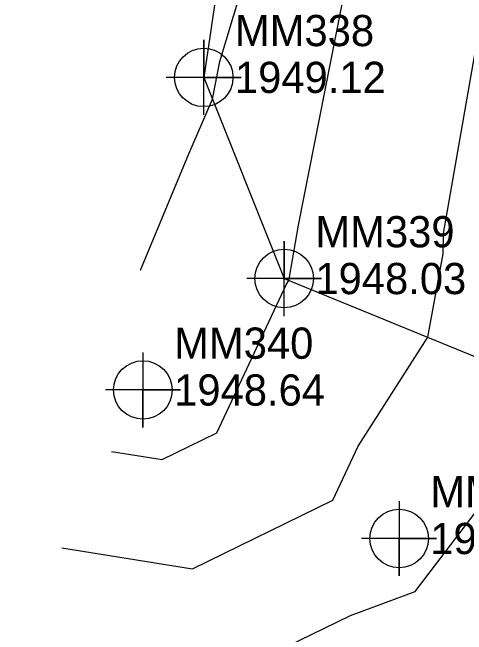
# Model space of a CAD drawing. Extents: x 1004378 to 1005103, y 553854 to 554288.
# Drawn here: x 1004892.91 to 1004929.28, y 553980.98 to 554030.8 of the extents above; entities that cross this region are included whole.
import ezdxf

# ---------------------------------------------------------------- set-up
doc = ezdxf.new("R2010")
doc.units = 0
for name, color, linetype in [('DTM Contours Minor', 7, 'Continuous'), ('Exist DTM Regular Point CELL', 7, 'Continuous'), ('Exist DTM Regular Point Cogo Elevation', 7, 'Continuous'), ('Exist DTM Regular Point Cogo Number', 7, 'Continuous'), ('Exist Roads Soil', 7, 'Continuous'), ('Exist Roads Soil Cogo Elevation', 7, 'Continuous'), ('Exist Roads Soil Cogo Number', 7, 'Continuous'), ('Exist Roads Soil Cogo Point CELL', 7, 'Continuous')]:
    doc.layers.add(name, color=color, linetype=linetype)

msp = doc.modelspace()

# ---------------------------------------------------------------- linework, layer by layer
at = {"layer": 'DTM Contours Minor'}
for points in [[(1004892.909, 553980.228), (1004909.736, 553977.519), (1004919.988, 553982.517), (1004925.173, 553984.426), (1004936.898, 553999.835), (1004937.254, 554000.219), (1004937.418, 554000.896), (1004939.715, 554013.407), (1004939.746, 554016.607), (1004940.982, 554023.681), (1004941.12, 554046.622), (1004942.146, 554051.575), (1004941.271, 554057.545), (1004943.194, 554079.367), (1004940.844, 554083.886), (1004927.509, 554103.798), (1004927.675, 554104.761), (1004926.297, 554106.983), (1004913.409, 554117.504), (1004910.609, 554119.787), (1004911.321, 554123.435)], [(1004896.871, 553987.94), (1004907.319, 553986.258), (1004918.577, 553991.746), (1004920.602, 553996.072), (1004926.171, 554004.786), (1004927.401, 554011.483), (1004927.417, 554013.109), (1004930.834, 554032.674), (1004930.895, 554042.816), (1004933.912, 554057.37), (1004933.33, 554061.338), (1004934.608, 554075.845), (1004923.665, 554096.889), (1004921.296, 554100.426), (1004922.463, 554107.183), (1004921.461, 554108.798), (1004912.095, 554116.444), (1004910.06, 554118.103), (1004910.577, 554120.754)], [(1004900.833, 553995.652), (1004904.901, 553994.997), (1004909.285, 553997.134), (1004914.864, 554009.051), (1004915.047, 554009.338), (1004915.087, 554009.558), (1004915.088, 554009.611), (1004915.812, 554013.756), (1004920.511, 554037.575), (1004921.349, 554040.369), (1004921.885, 554044.869), (1004925.677, 554063.164), (1004925.388, 554065.131), (1004926.022, 554072.322), (1004918.902, 554086.015), (1004916.128, 554095.112), (1004916.311, 554104.166), (1004917.251, 554109.606), (1004916.626, 554110.613), (1004910.781, 554115.385), (1004909.511, 554116.42), (1004909.834, 554118.074)], [(1004903.159, 554010.176), (1004907.034, 554019.468), (1004908.926, 554023.854), (1004909.52, 554026.862), (1004914.391, 554043.11), (1004917.359, 554068.029), (1004917.408, 554068.634), (1004917.453, 554068.931), (1004916.926, 554070.64), (1004911.247, 554089.262), (1004911.665, 554109.865), (1004912.038, 554112.028), (1004911.79, 554112.428), (1004909.467, 554114.325), (1004908.962, 554114.737), (1004909.09, 554115.394)]]:
    msp.add_lwpolyline(points, dxfattribs=at)
at = {"layer": 'Exist DTM Regular Point CELL'}
for points in [[(1004903.359, 554003.569), (1004903.359, 553997.569), (1004903.359, 554000.569), (1004906.359, 554000.569), (1004900.359, 554000.569)], [(1004923.872, 553991.677), (1004923.872, 553985.677), (1004923.872, 553988.677), (1004926.872, 553988.677), (1004920.872, 553988.677)]]:
    msp.add_lwpolyline(points, dxfattribs=at)
for centre in [(1004903.359, 554000.569), (1004923.872, 553988.677)]:
    msp.add_circle(centre, 2.344, dxfattribs=at)
at = {"layer": 'Exist Roads Soil'}
msp.add_lwpolyline([(1004902.345, 554049.201), (1004911.013, 554044.44), (1004908.227, 554025.602), (1004914.669, 554009.493), (1004937.036, 554000.34), (1004928.257, 553968.154), (1004911.901, 553969.693), (1004894.395, 553961.828)], dxfattribs=at)
at = {"layer": 'Exist Roads Soil Cogo Point CELL'}
for points in [[(1004908.227, 554022.602), (1004908.227, 554028.602), (1004908.227, 554025.602), (1004911.227, 554025.602), (1004905.227, 554025.602)], [(1004914.669, 554006.493), (1004914.669, 554012.493), (1004914.669, 554009.493), (1004917.669, 554009.493), (1004911.669, 554009.493)]]:
    msp.add_lwpolyline(points, dxfattribs=at)
for centre in [(1004908.227, 554025.602), (1004914.669, 554009.493)]:
    msp.add_circle(centre, 2.344, dxfattribs=at)

# ---------------------------------------------------------------- texts
at = {"layer": 'Exist DTM Regular Point Cogo Elevation'}
for s, p in [('1948.64', (1004905.859, 553999.319)), ('1946.43', (1004926.372, 553987.427))]:
    msp.add_text(s, height=2.5, dxfattribs=at).set_placement(p)
at = {"layer": 'Exist DTM Regular Point Cogo Number'}
for s, p in [('MM340', (1004905.859, 554003.069)), ('MM382', (1004926.372, 553991.177))]:
    msp.add_text(s, height=2.5, dxfattribs=at).set_placement(p)
at = {"layer": 'Exist Roads Soil Cogo Elevation'}
for s, p in [('1949.12', (1004910.727, 554024.352)), ('1948.03', (1004917.169, 554008.243))]:
    msp.add_text(s, height=2.5, dxfattribs=at).set_placement(p)
at = {"layer": 'Exist Roads Soil Cogo Number'}
for s, p in [('MM338', (1004910.727, 554028.102)), ('MM339', (1004917.169, 554011.993))]:
    msp.add_text(s, height=2.5, dxfattribs=at).set_placement(p)

doc.saveas('drawing.dxf')
